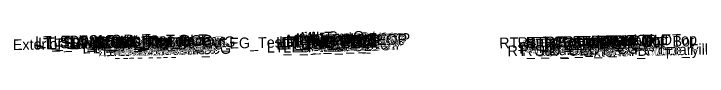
# Model space of a CAD drawing. Extents: x 118 to 4243, y 0 to 9511.
# Drawn here: x 3133 to 3262.3, y 2500 to 2505.3 of the extents above; entities that cross this region are included whole.
import ezdxf

# ---------------------------------------------------------------- set-up
doc = ezdxf.new("R2010")
doc.units = 0
doc.layers.add('Scratch_Level_0', color=7, linetype='Continuous')

msp = doc.modelspace()

# ---------------------------------------------------------------- texts
at = {"layer": 'Scratch_Level_0'}
for s, p in [('Exterior Boundary', (3132.85, 2501.71)), ('LT_SDWK_Out_Top', (3137.01, 2502.28)), ('LT_SDWK_Out_Bot', (3137.04, 2501.94)), ('LT_Sub_Trench_Out_DLT', (3137.57, 2502.03)), ('LT_Slope_Fill', (3139.22, 2501.84)), ('LT_CSLP_Pnt', (3140.44, 2502.35)), ('LT_SDWK_In_Top', (3143.63, 2502.21)), ('LT_SDWK_In_Bot', (3143.66, 2501.88)), ('LT_PV_Sub_Tie_Out', (3147.23, 2501.76)), ('LT_CG_Top_Face', (3147.53, 2502.11)), ('LT_CG_Top_BOC', (3148.05, 2502.13)), ('LT_PV_OEEOP_EG', (3149.82, 2501.81)), ('LT_PV1_OEOT', (3153.01, 2501.8)), ('LT_PV_EG_TestPt', (3163.56, 2501.81)), ('LT_PV2_IEEOP', (3181.97, 2502.13)), ('LT_PV3_IEEOP', (3181.97, 2501.79)), ('LT_PV1_IEEOP', (3182.54, 2502.26)), ('LT_PV2_PGL1', (3182.9, 2502.14)), ('LT_PV3_PGL1', (3182.9, 2501.81)), ('LT_PV2_PGL', (3183.23, 2502.15)), ('LT_PV3_PGL', (3183.23, 2501.82)), ('LT_PV1_PGL', (3183.8, 2502.41)), ('MI_Face In', (3183.92, 2502.58)), ('RT_PV2_OEEOP', (3185.28, 2502.35)), ('RT_PV3_OEEOP', (3185.28, 2502.02)), ('MI_Top In', (3185.63, 2502.85)), ('RT_PV1_OEEOP', (3185.85, 2502.49)), ('RT_PV2_IEEOP', (3185.93, 2502.36)), ('MI_Face Out', (3186.28, 2502.79)), ('MI_Top Out', (3186.49, 2503.06)), ('RT_PV1_IEEOP', (3186.49, 2502.5)), ('RT_PV2_PGL1', (3186.86, 2502.38)), ('RT_PV3_PGL1', (3186.86, 2502.05)), ('MI_Crown', (3187.09, 2503.12)), ('RT_PV2_PGL', (3187.19, 2502.39)), ('MI_Bot Out', (3187.28, 2502.64)), ('RT_PV1_PGL', (3187.75, 2502.65)), ('RT_Sub_Trench_Out_DLT', (3223.56, 2502.03)), ('RT_CG_Top_Face', (3226.99, 2502.11)), ('RT_PV1_OEOT', (3228.46, 2501.79)), ('RT_CG_Top_BOC', (3228.51, 2502.13)), ('RT_SDWK_In_Top', (3232.08, 2502.21)), ('RT_SDWK_In_Bot', (3232.11, 2501.87)), ('RT_SDWK_Out_Top', (3235.46, 2502.27)), ('RT_SDWK_Out_Bot', (3235.49, 2501.94)), ('RT_Shld_O', (3241.81, 2502.39)), ('CSLP_Pnt', (3242.64, 2502.41)), ('LT_CG1_Shelf_Out', (3145.82, 2501.07)), ('LT_CG_Bot_BOC', (3148.09, 2501.11)), ('LT_CG_Top_Gut', (3148.51, 2501.63)), ('LT_Sub_OEOP', (3148.79, 2500.54)), ('LT_Sub_OEOT_CG', (3149.64, 2500.56)), ('LT_Sub_OEEOP', (3151.48, 2500.6)), ('LT_PV2_OEEOP', (3151.58, 2501.52)), ('LT_PV3_OEEOP', (3151.58, 2501.18)), ('LT_PV1_OEEOP', (3152.15, 2501.65)), ('LT_CG_Bot_IE', (3152.19, 2501.2)), ('LT_Sub_OEOT', (3152.35, 2500.62)), ('LT_PV2_OEOT', (3152.45, 2501.53)), ('LT_PV3_OEOT', (3152.45, 2501.2)), ('LT_PV_IEEOP_EG', (3180.21, 2501.23)), ('LT_PV4_PGL', (3183.23, 2501.23)), ('RT_Sub_OEEOP', (3185.19, 2501.43)), ('RT_PV4_PGL', (3187.19, 2501.47)), ('RT_Sub_OEOT_CG', (3225.1, 2500.56)), ('RT_CG1_Shelf_Out', (3227.28, 2501.07)), ('RT_CG_Bot_IE', (3227.64, 2501.2)), ('RT_Sub_OEOT', (3227.8, 2500.61)), ('RT_PV2_OEOT', (3227.9, 2501.53)), ('RT_PV3_OEOT', (3227.9, 2501.2)), ('RT_CG_Top_Gut', (3227.96, 2501.62)), ('RT_CG_Bot_BOC', (3228.54, 2501.11)), ('RT_Sub_OEOP', (3231.43, 2500.54)), ('Exterior Boundary', (3239.36, 2500.42)), ('RT_Slope_Fill', (3245.69, 2500.55))]:
    msp.add_text(s, height=2, rotation=1.1458, dxfattribs=at).set_placement(p)

doc.saveas('drawing.dxf')
